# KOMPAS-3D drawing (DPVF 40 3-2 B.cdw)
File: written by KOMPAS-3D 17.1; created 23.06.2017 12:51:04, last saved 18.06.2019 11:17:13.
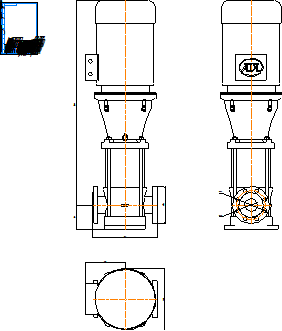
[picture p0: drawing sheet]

Sheet 1: A4, portrait

Title block, sheet 1: name: DPVF 40 3-2 B; material: Внимание! Данный продукт является объектом авторского права ООО «Торговый Дом АДЛ». / Запрещается изменение, копирование, распространение / (в том числе путем копирования на другие сайты и ресурсы в Интернете) / или любое иное использование информации и объектов без предварительного / согласия правообладателя (ООО «Торговый Дом АДЛ»).; scale: 1:1; sheets: 1; organisation: ООО "Торговый дом АДЛ"; sheet format: A4; stored path: C:\Клочков АВ\Насосы\DP PAMS\DPVF 40\Компас 2d\DPVF 40 3-2 B.cdw

Views: Спереди 1
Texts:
  Клочков АВ
  ООО АДЛ ГРУПП
Dimensions and other numbers on the sheet: 365; 223; 350; 209,6; 1156,5; 140; 168,1; 76,2; 1:1; 1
